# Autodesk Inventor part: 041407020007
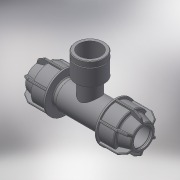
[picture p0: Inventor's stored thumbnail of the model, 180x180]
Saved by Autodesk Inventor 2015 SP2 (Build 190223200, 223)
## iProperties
Created: 2017-08
Part Number: 041407020007
Material: Generic
Description: PLASSON IRRIFIT TEE FEMALE ADAPTOR 20-3/4"-20
Document SubType Name: Modeling
Designer: KIM
Density: 1 g/cm^3
Appearance: Default
Author: KIM
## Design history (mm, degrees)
derived "041407.ipt"
feature "Solid1::041407.ipt"
feature "Solid2::041407.ipt"
tag "TaggingFeature1"
body "Solid1"
other parameters: "d2" = 25, "d4" = 15 deg, "d5" = 23.75, "d6" = 9.5, "d10" = 39, "d16" = 20.4, "d17" = 1.25, "d22" = 26, "d24" = 1.25, "d25" = 35.1, "d26" = 29.25, "d27" = 1.25, "d28" = 135 deg, "d29" = 0.75, "d31" = 1, "d46" = 150 deg, "d49" = 1.95, "d50" = 0, "d58" = 0.6, "d61" = 360 deg, "d63" = 18, "d64" = 45, "d80" = 28.6, "d81" = 0.2, "d94" = 46, "d96" = 31.3521, "d108" = 0.6, "d113" = 16.8819, "d115" = 20.4, "d117" = 21.7053, "d118" = 2.5, "d119" = 17, "d120" = 24.117, "d121" = 0.48234, "d122" = 5.1, "d123" = 2.5, "d128" = 31.3521, "d130" = 0, "d132" = 0, "G_" = 24.117, "E_" = 39, "l_" = 25, "l_1" = 17, "A_" = 46
